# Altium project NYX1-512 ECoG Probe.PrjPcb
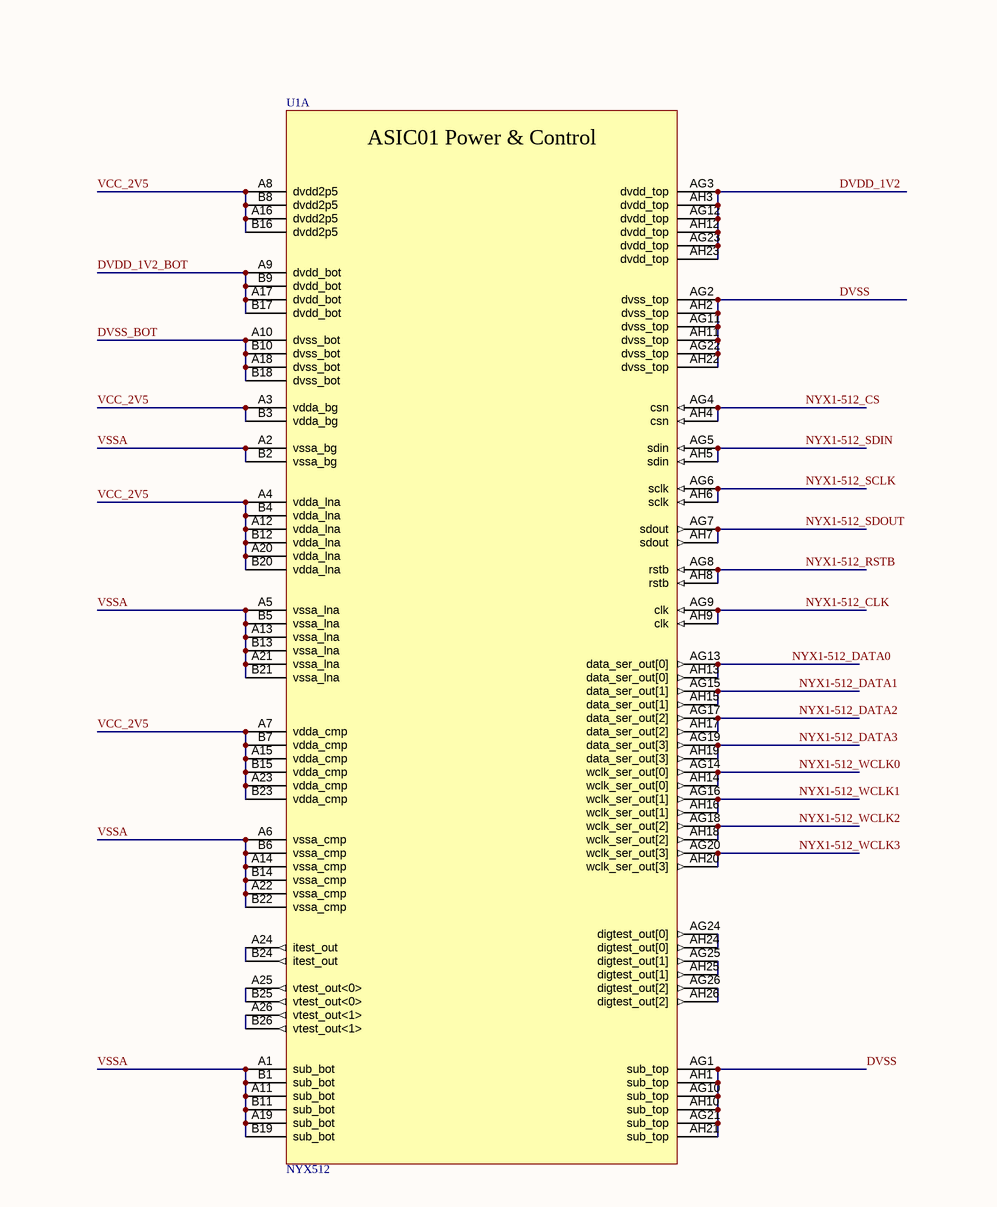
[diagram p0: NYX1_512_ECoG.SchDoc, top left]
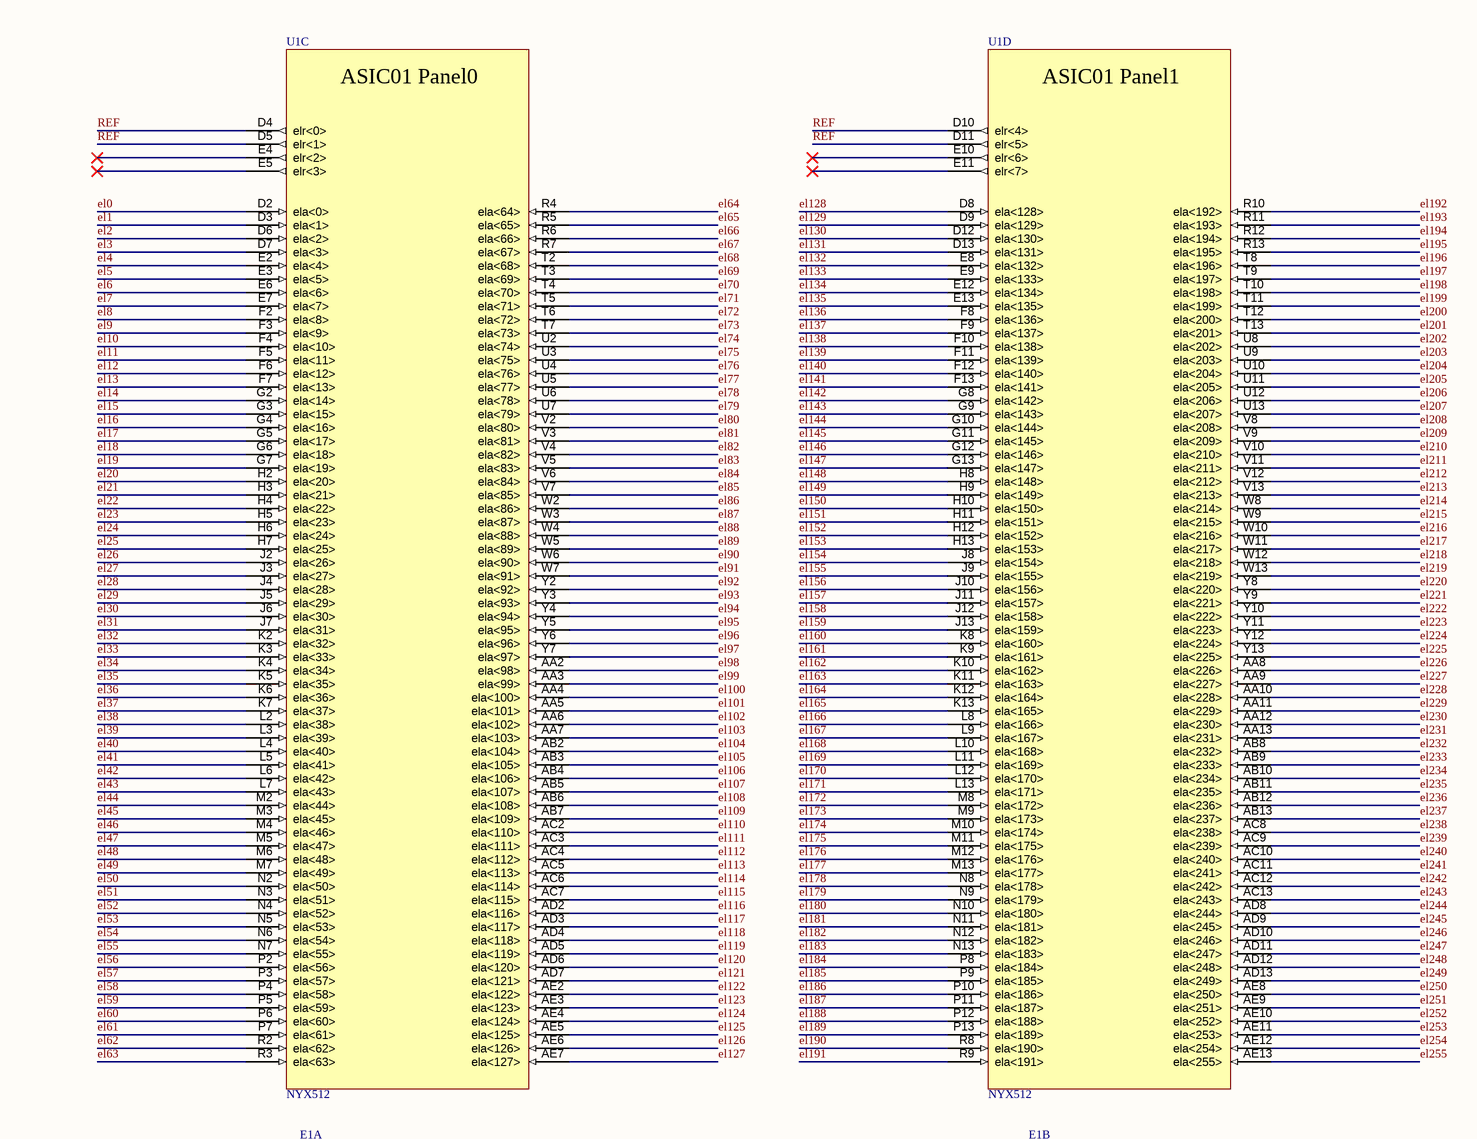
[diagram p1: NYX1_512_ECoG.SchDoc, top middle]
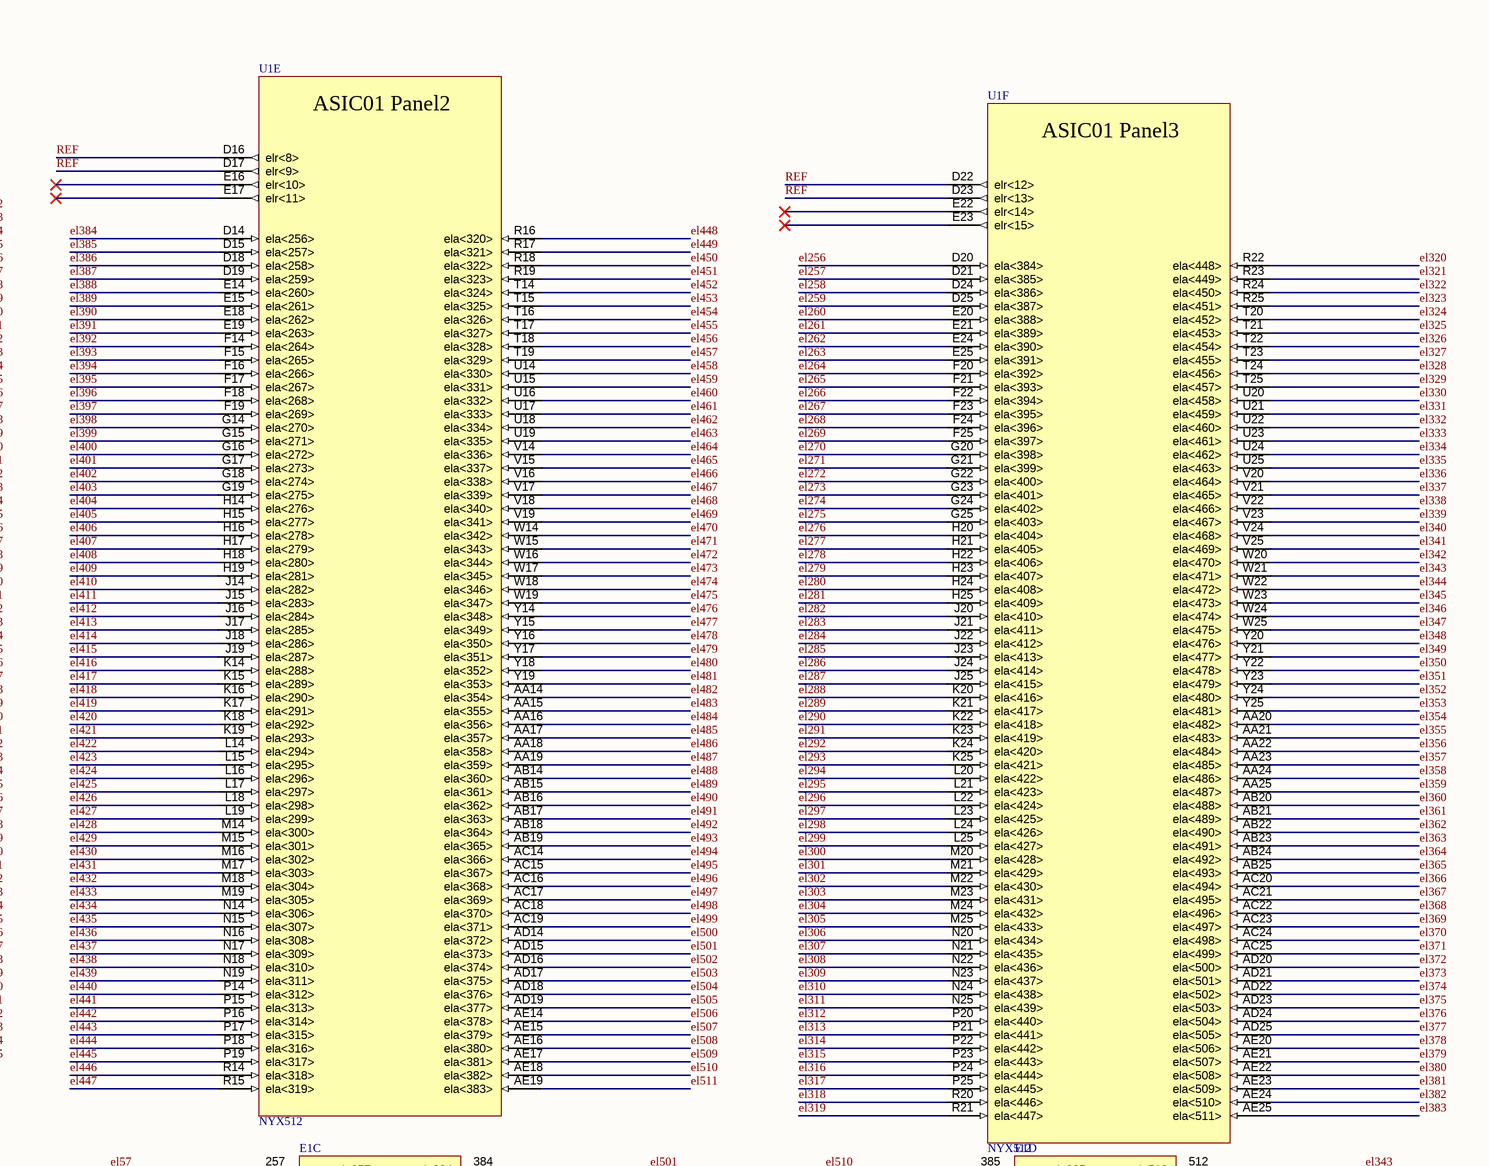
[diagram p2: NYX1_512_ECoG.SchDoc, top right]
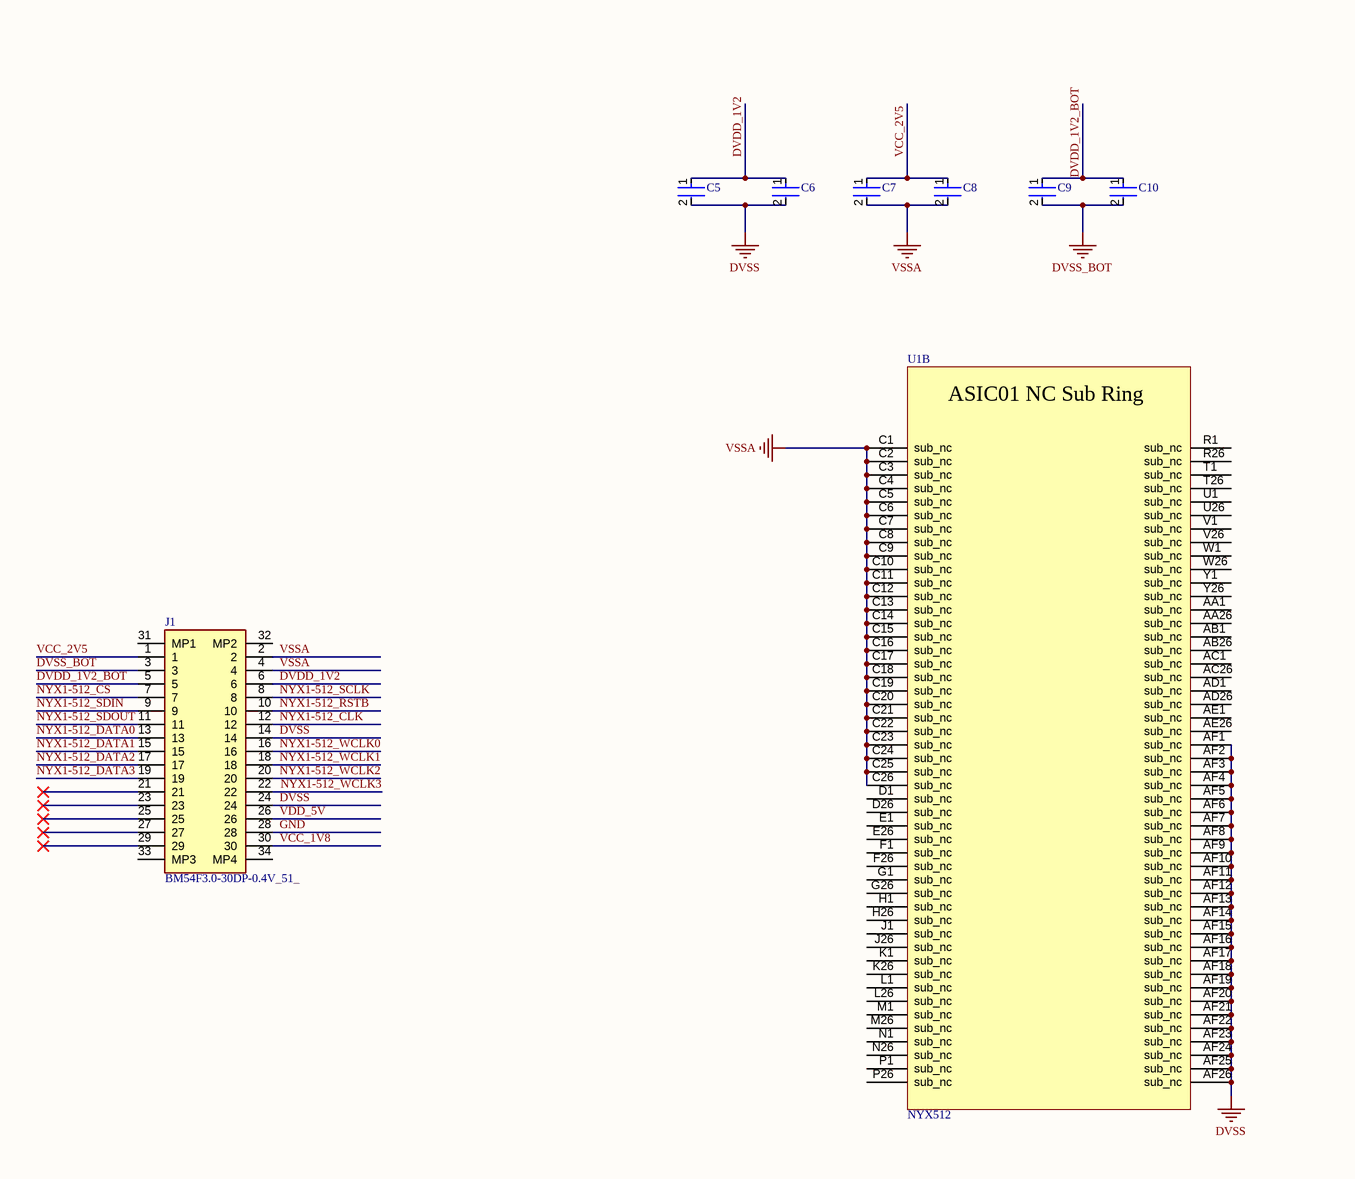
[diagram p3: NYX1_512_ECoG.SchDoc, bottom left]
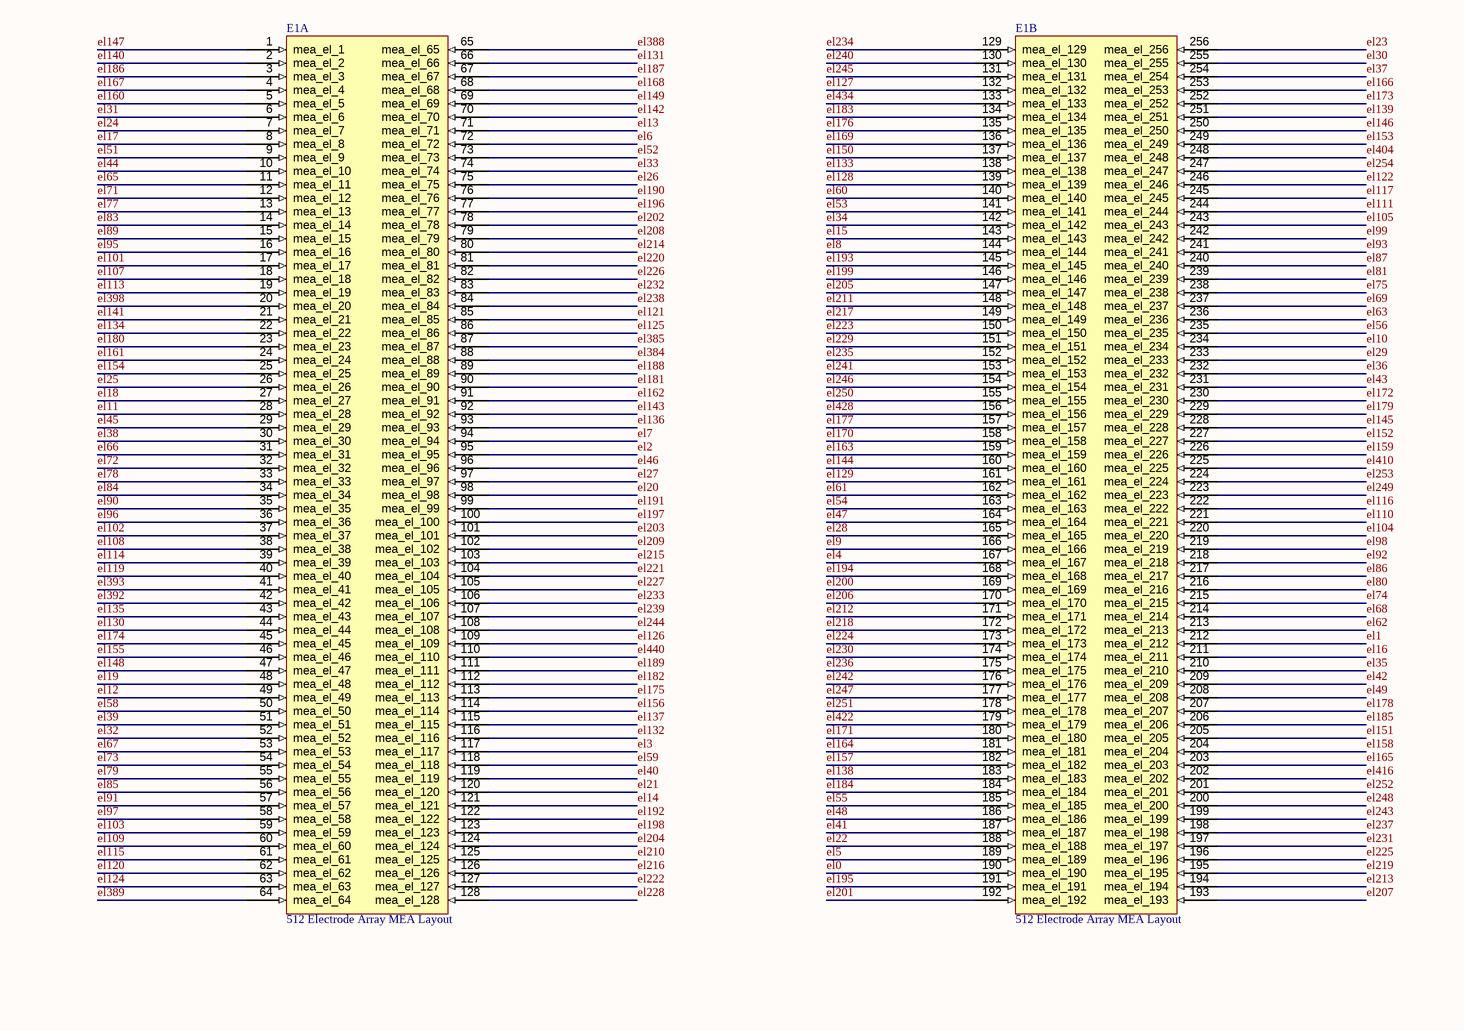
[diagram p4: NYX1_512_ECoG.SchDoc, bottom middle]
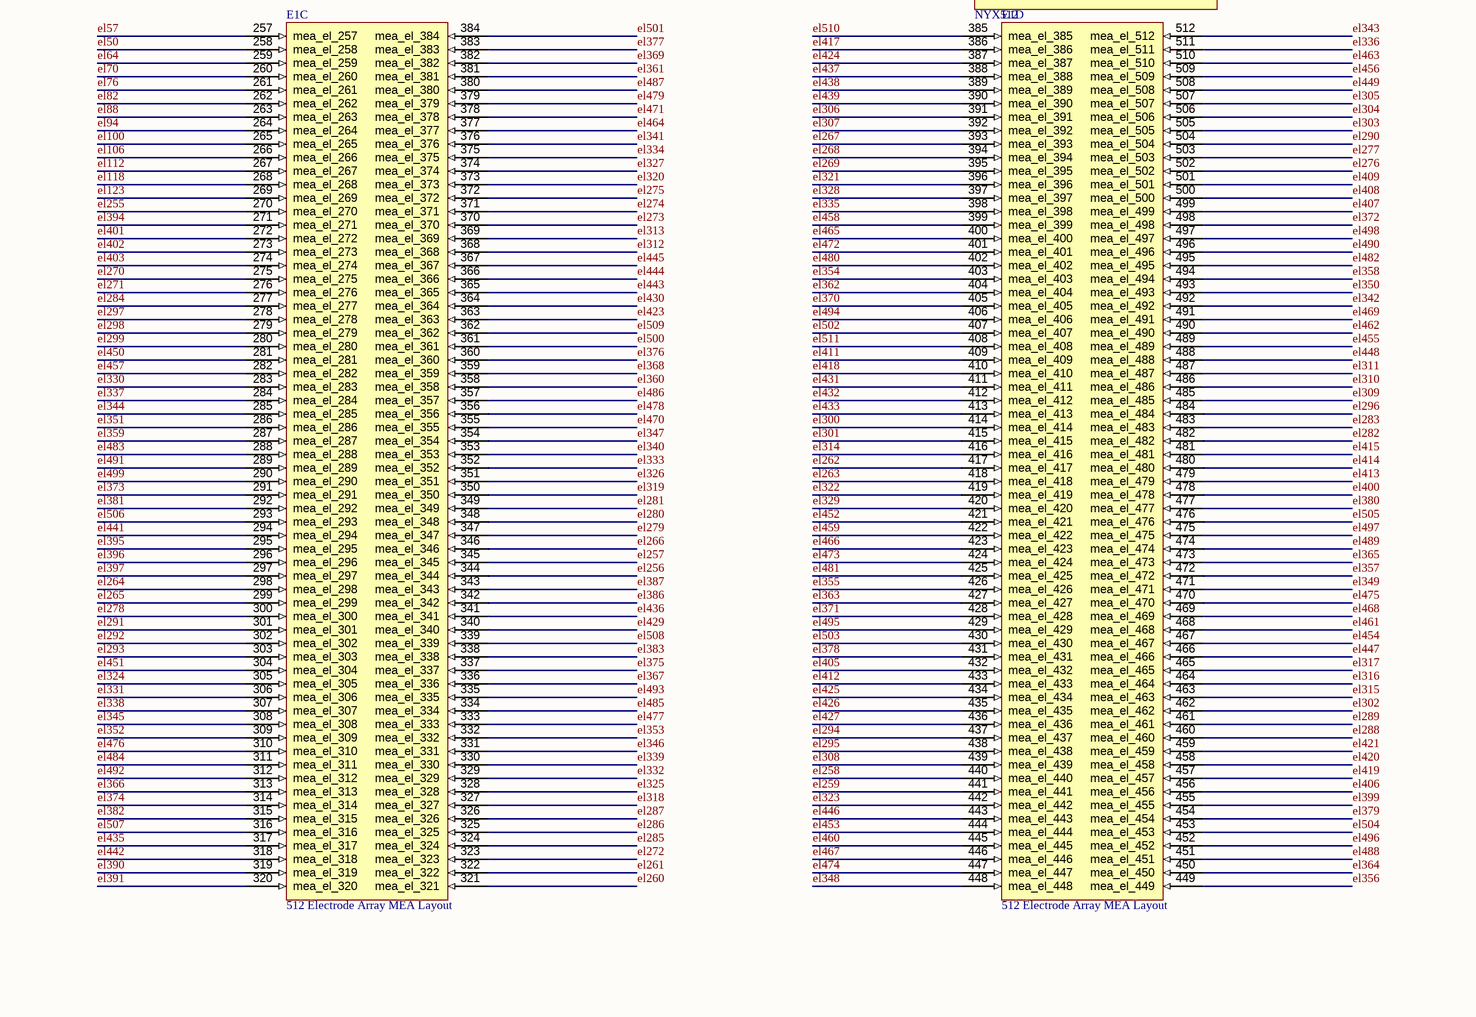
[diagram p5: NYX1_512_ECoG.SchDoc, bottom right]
Title: NYX1-512 ECoG Probe; Revision: A; Project: NYX1-512; Organization: Science Corporation; ENG_APP_DATE: 5/19/26; Engineer: Max Rothman; Address3: USA; Address2: Alameda CA 94501; Address1: 300 Wind River Way
1 sheet, 9 parts. Net scope: global (net labels, ports and power ports of the same name join across sheets).
Board file: NYX1_512_ECoG.PcbDoc

## Sheet NYX1_512_ECoG.SchDoc: NYX1-512 ECoG Probe
size 863 x 558 mm; SheetNumber: 2; SheetTotal: 2

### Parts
C5  GRT155R61E105KE01D  [FP-GRT155-0_05-MFG]  (value not drawn)
C6  CC0402KRX7R9BB104  [FP-CC0402-MFG]  (value not drawn)
C7  GRT155R61E105KE01D  [FP-GRT155-0_05-MFG]  (value not drawn)
C8  CC0402KRX7R9BB104  [FP-CC0402-MFG]  (value not drawn)
C9  GRT155R61E105KE01D  [FP-GRT155-0_05-MFG]  (value not drawn)
C10  CC0402KRX7R9BB104  [FP-CC0402-MFG]  (value not drawn)
E1  512 Electrode Array MEA Layout  [512 Electrode Array-Footprint-1]  (parts A,B,C,D of 4)
J1  BM54F3.0-30DP-0.4V_51_  [BM54F3030DP04V51]
U1  NYX512  [NYX512_footprint]  (parts A,B,C,D,E,F of 6)

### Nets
DVSS: C5.2 C6.2 J1.14 J1.24 U1.AF1(sub_nc) U1.AF2(sub_nc) U1.AF3(sub_nc) U1.AF4(sub_nc) U1.AF5(sub_nc) U1.AF6(sub_nc) U1.AF7(sub_nc) U1.AF8(sub_nc) U1.AF9(sub_nc) U1.AF10(sub_nc) U1.AF11(sub_nc) U1.AF12(sub_nc) U1.AF13(sub_nc) U1.AF14(sub_nc) U1.AF15(sub_nc) U1.AF16(sub_nc) U1.AF17(sub_nc) U1.AF18(sub_nc) U1.AF19(sub_nc) U1.AF20(sub_nc) U1.AF21(sub_nc) U1.AF22(sub_nc) U1.AF23(sub_nc) U1.AF24(sub_nc) U1.AF25(sub_nc) U1.AF26(sub_nc) U1.AG1(sub_top) U1.AG2(dvss_top) U1.AG10(sub_top) U1.AG11(dvss_top) U1.AG21(sub_top) U1.AG22(dvss_top) U1.AH1(sub_top) U1.AH2(dvss_top) U1.AH10(sub_top) U1.AH11(dvss_top) U1.AH21(sub_top) U1.AH22(dvss_top)
DVSS_BOT: C9.2 C10.2 J1.3 U1.A10(dvss_bot) U1.A18(dvss_bot) U1.B10(dvss_bot) U1.B18(dvss_bot)
VSSA: C7.2 C8.2 J1.2 J1.4 U1.A1(sub_bot) U1.A2(vssa_bg) U1.A5(vssa_lna) U1.A6(vssa_cmp) U1.A11(sub_bot) U1.A13(vssa_lna) U1.A14(vssa_cmp) U1.A19(sub_bot) U1.A21(vssa_lna) U1.A22(vssa_cmp) U1.B1(sub_bot) U1.B2(vssa_bg) U1.B5(vssa_lna) U1.B6(vssa_cmp) U1.B11(sub_bot) U1.B13(vssa_lna) U1.B14(vssa_cmp) U1.B19(sub_bot) U1.B21(vssa_lna) U1.B22(vssa_cmp) U1.C1(sub_nc) U1.C2(sub_nc) U1.C3(sub_nc) U1.C4(sub_nc) U1.C5(sub_nc) U1.C6(sub_nc) U1.C7(sub_nc) U1.C8(sub_nc) U1.C9(sub_nc) U1.C10(sub_nc) U1.C11(sub_nc) U1.C12(sub_nc) U1.C13(sub_nc) U1.C14(sub_nc) U1.C15(sub_nc) U1.C16(sub_nc) U1.C17(sub_nc) U1.C18(sub_nc) U1.C19(sub_nc) U1.C20(sub_nc) U1.C21(sub_nc) U1.C22(sub_nc) U1.C23(sub_nc) U1.C24(sub_nc) U1.C25(sub_nc) U1.C26(sub_nc)
DVDD_1V2: C5.1 C6.1 J1.6 U1.AG3(dvdd_top) U1.AG12(dvdd_top) U1.AG23(dvdd_top) U1.AH3(dvdd_top) U1.AH12(dvdd_top) U1.AH23(dvdd_top)
DVDD_1V2_BOT: C9.1 C10.1 J1.5 U1.A9(dvdd_bot) U1.A17(dvdd_bot) U1.B9(dvdd_bot) U1.B17(dvdd_bot)
el0: E1.190(mea_el_190) U1.D2(ela<0>)
el1: E1.212(mea_el_212) U1.D3(ela<1>)
el2: E1.95(mea_el_95) U1.D6(ela<2>)
el3: E1.117(mea_el_117) U1.D7(ela<3>)
el4: E1.167(mea_el_167) U1.E2(ela<4>)
el5: E1.189(mea_el_189) U1.E3(ela<5>)
el6: E1.72(mea_el_72) U1.E6(ela<6>)
el7: E1.94(mea_el_94) U1.E7(ela<7>)
el8: E1.144(mea_el_144) U1.F2(ela<8>)
el9: E1.166(mea_el_166) U1.F3(ela<9>)
el10: E1.234(mea_el_234) U1.F4(ela<10>)
el11: E1.28(mea_el_28) U1.F5(ela<11>)
el12: E1.49(mea_el_49) U1.F6(ela<12>)
el13: E1.71(mea_el_71) U1.F7(ela<13>)
el14: E1.121(mea_el_121) U1.G2(ela<14>)
el15: E1.143(mea_el_143) U1.G3(ela<15>)
el16: E1.211(mea_el_211) U1.G4(ela<16>)
el17: E1.8(mea_el_8) U1.G5(ela<17>)
el18: E1.27(mea_el_27) U1.G6(ela<18>)
el19: E1.48(mea_el_48) U1.G7(ela<19>)
el20: E1.98(mea_el_98) U1.H2(ela<20>)
el21: E1.120(mea_el_120) U1.H3(ela<21>)
el22: E1.188(mea_el_188) U1.H4(ela<22>)
el23: E1.256(mea_el_256) U1.H5(ela<23>)
el24: E1.7(mea_el_7) U1.H6(ela<24>)
el25: E1.26(mea_el_26) U1.H7(ela<25>)
el26: E1.75(mea_el_75) U1.J2(ela<26>)
el27: E1.97(mea_el_97) U1.J3(ela<27>)
el28: E1.165(mea_el_165) U1.J4(ela<28>)
el29: E1.233(mea_el_233) U1.J5(ela<29>)
el30: E1.255(mea_el_255) U1.J6(ela<30>)
el31: E1.6(mea_el_6) U1.J7(ela<31>)
el32: E1.52(mea_el_52) U1.K2(ela<32>)
el33: E1.74(mea_el_74) U1.K3(ela<33>)
el34: E1.142(mea_el_142) U1.K4(ela<34>)
el35: E1.210(mea_el_210) U1.K5(ela<35>)
el36: E1.232(mea_el_232) U1.K6(ela<36>)
el37: E1.254(mea_el_254) U1.K7(ela<37>)
el38: E1.30(mea_el_30) U1.L2(ela<38>)
el39: E1.51(mea_el_51) U1.L3(ela<39>)
el40: E1.119(mea_el_119) U1.L4(ela<40>)
el41: E1.187(mea_el_187) U1.L5(ela<41>)
el42: E1.209(mea_el_209) U1.L6(ela<42>)
el43: E1.231(mea_el_231) U1.L7(ela<43>)
el44: E1.10(mea_el_10) U1.M2(ela<44>)
el45: E1.29(mea_el_29) U1.M3(ela<45>)
el46: E1.96(mea_el_96) U1.M4(ela<46>)
el47: E1.164(mea_el_164) U1.M5(ela<47>)
el48: E1.186(mea_el_186) U1.M6(ela<48>)
el49: E1.208(mea_el_208) U1.M7(ela<49>)
el50: E1.258(mea_el_258) U1.N2(ela<50>)
el51: E1.9(mea_el_9) U1.N3(ela<51>)
el52: E1.73(mea_el_73) U1.N4(ela<52>)
el53: E1.141(mea_el_141) U1.N5(ela<53>)
el54: E1.163(mea_el_163) U1.N6(ela<54>)
el55: E1.185(mea_el_185) U1.N7(ela<55>)
el56: E1.235(mea_el_235) U1.P2(ela<56>)
el57: E1.257(mea_el_257) U1.P3(ela<57>)
el58: E1.50(mea_el_50) U1.P4(ela<58>)
el59: E1.118(mea_el_118) U1.P5(ela<59>)
el60: E1.140(mea_el_140) U1.P6(ela<60>)
el61: E1.162(mea_el_162) U1.P7(ela<61>)
el62: E1.213(mea_el_213) U1.R2(ela<62>)
el63: E1.236(mea_el_236) U1.R3(ela<63>)
el64: E1.259(mea_el_259) U1.R4(ela<64>)
el65: E1.11(mea_el_11) U1.R5(ela<65>)
el66: E1.31(mea_el_31) U1.R6(ela<66>)
el67: E1.53(mea_el_53) U1.R7(ela<67>)
el68: E1.214(mea_el_214) U1.T2(ela<68>)
el69: E1.237(mea_el_237) U1.T3(ela<69>)
el70: E1.260(mea_el_260) U1.T4(ela<70>)
el71: E1.12(mea_el_12) U1.T5(ela<71>)
el72: E1.32(mea_el_32) U1.T6(ela<72>)
el73: E1.54(mea_el_54) U1.T7(ela<73>)
el74: E1.215(mea_el_215) U1.U2(ela<74>)
el75: E1.238(mea_el_238) U1.U3(ela<75>)
el76: E1.261(mea_el_261) U1.U4(ela<76>)
el77: E1.13(mea_el_13) U1.U5(ela<77>)
el78: E1.33(mea_el_33) U1.U6(ela<78>)
el79: E1.55(mea_el_55) U1.U7(ela<79>)
el80: E1.216(mea_el_216) U1.V2(ela<80>)
el81: E1.239(mea_el_239) U1.V3(ela<81>)
el82: E1.262(mea_el_262) U1.V4(ela<82>)
el83: E1.14(mea_el_14) U1.V5(ela<83>)
el84: E1.34(mea_el_34) U1.V6(ela<84>)
el85: E1.56(mea_el_56) U1.V7(ela<85>)
el86: E1.217(mea_el_217) U1.W2(ela<86>)
el87: E1.240(mea_el_240) U1.W3(ela<87>)
el88: E1.263(mea_el_263) U1.W4(ela<88>)
el89: E1.15(mea_el_15) U1.W5(ela<89>)
el90: E1.35(mea_el_35) U1.W6(ela<90>)
el91: E1.57(mea_el_57) U1.W7(ela<91>)
el92: E1.218(mea_el_218) U1.Y2(ela<92>)
el93: E1.241(mea_el_241) U1.Y3(ela<93>)
el94: E1.264(mea_el_264) U1.Y4(ela<94>)
el95: E1.16(mea_el_16) U1.Y5(ela<95>)
el96: E1.36(mea_el_36) U1.Y6(ela<96>)
el97: E1.58(mea_el_58) U1.Y7(ela<97>)
el98: E1.219(mea_el_219) U1.AA2(ela<98>)
el99: E1.242(mea_el_242) U1.AA3(ela<99>)
el100: E1.265(mea_el_265) U1.AA4(ela<100>)
el101: E1.17(mea_el_17) U1.AA5(ela<101>)
el102: E1.37(mea_el_37) U1.AA6(ela<102>)
el103: E1.59(mea_el_59) U1.AA7(ela<103>)
el104: E1.220(mea_el_220) U1.AB2(ela<104>)
el105: E1.243(mea_el_243) U1.AB3(ela<105>)
el106: E1.266(mea_el_266) U1.AB4(ela<106>)
el107: E1.18(mea_el_18) U1.AB5(ela<107>)
el108: E1.38(mea_el_38) U1.AB6(ela<108>)
el109: E1.60(mea_el_60) U1.AB7(ela<109>)
el110: E1.221(mea_el_221) U1.AC2(ela<110>)
el111: E1.244(mea_el_244) U1.AC3(ela<111>)
el112: E1.267(mea_el_267) U1.AC4(ela<112>)
el113: E1.19(mea_el_19) U1.AC5(ela<113>)
el114: E1.39(mea_el_39) U1.AC6(ela<114>)
el115: E1.61(mea_el_61) U1.AC7(ela<115>)
el116: E1.222(mea_el_222) U1.AD2(ela<116>)
el117: E1.245(mea_el_245) U1.AD3(ela<117>)
el118: E1.268(mea_el_268) U1.AD4(ela<118>)
el119: E1.40(mea_el_40) U1.AD5(ela<119>)
el120: E1.62(mea_el_62) U1.AD6(ela<120>)
el121: E1.85(mea_el_85) U1.AD7(ela<121>)
el122: E1.246(mea_el_246) U1.AE2(ela<122>)
el123: E1.269(mea_el_269) U1.AE3(ela<123>)
el124: E1.63(mea_el_63) U1.AE4(ela<124>)
el125: E1.86(mea_el_86) U1.AE5(ela<125>)
el126: E1.109(mea_el_109) U1.AE6(ela<126>)
el127: E1.132(mea_el_132) U1.AE7(ela<127>)
el128: E1.139(mea_el_139) U1.D8(ela<128>)
el129: E1.161(mea_el_161) U1.D9(ela<129>)
el130: E1.44(mea_el_44) U1.D12(ela<130>)
el131: E1.66(mea_el_66) U1.D13(ela<131>)
el132: E1.116(mea_el_116) U1.E8(ela<132>)
el133: E1.138(mea_el_138) U1.E9(ela<133>)
el134: E1.22(mea_el_22) U1.E12(ela<134>)
el135: E1.43(mea_el_43) U1.E13(ela<135>)
el136: E1.93(mea_el_93) U1.F8(ela<136>)
el137: E1.115(mea_el_115) U1.F9(ela<137>)
el138: E1.183(mea_el_183) U1.F10(ela<138>)
el139: E1.251(mea_el_251) U1.F11(ela<139>)
el140: E1.2(mea_el_2) U1.F12(ela<140>)
el141: E1.21(mea_el_21) U1.F13(ela<141>)
el142: E1.70(mea_el_70) U1.G8(ela<142>)
el143: E1.92(mea_el_92) U1.G9(ela<143>)
el144: E1.160(mea_el_160) U1.G10(ela<144>)
el145: E1.228(mea_el_228) U1.G11(ela<145>)
el146: E1.250(mea_el_250) U1.G12(ela<146>)
el147: E1.1(mea_el_1) U1.G13(ela<147>)
el148: E1.47(mea_el_47) U1.H8(ela<148>)
el149: E1.69(mea_el_69) U1.H9(ela<149>)
el150: E1.137(mea_el_137) U1.H10(ela<150>)
el151: E1.205(mea_el_205) U1.H11(ela<151>)
el152: E1.227(mea_el_227) U1.H12(ela<152>)
el153: E1.249(mea_el_249) U1.H13(ela<153>)
el154: E1.25(mea_el_25) U1.J8(ela<154>)
el155: E1.46(mea_el_46) U1.J9(ela<155>)
el156: E1.114(mea_el_114) U1.J10(ela<156>)
el157: E1.182(mea_el_182) U1.J11(ela<157>)
el158: E1.204(mea_el_204) U1.J12(ela<158>)
el159: E1.226(mea_el_226) U1.J13(ela<159>)
el160: E1.5(mea_el_5) U1.K8(ela<160>)
el161: E1.24(mea_el_24) U1.K9(ela<161>)
el162: E1.91(mea_el_91) U1.K10(ela<162>)
el163: E1.159(mea_el_159) U1.K11(ela<163>)
el164: E1.181(mea_el_181) U1.K12(ela<164>)
el165: E1.203(mea_el_203) U1.K13(ela<165>)
el166: E1.253(mea_el_253) U1.L8(ela<166>)
el167: E1.4(mea_el_4) U1.L9(ela<167>)
el168: E1.68(mea_el_68) U1.L10(ela<168>)
el169: E1.136(mea_el_136) U1.L11(ela<169>)
el170: E1.158(mea_el_158) U1.L12(ela<170>)
el171: E1.180(mea_el_180) U1.L13(ela<171>)
el172: E1.230(mea_el_230) U1.M8(ela<172>)
el173: E1.252(mea_el_252) U1.M9(ela<173>)
el174: E1.45(mea_el_45) U1.M10(ela<174>)
el175: E1.113(mea_el_113) U1.M11(ela<175>)
el176: E1.135(mea_el_135) U1.M12(ela<176>)
el177: E1.157(mea_el_157) U1.M13(ela<177>)
el178: E1.207(mea_el_207) U1.N8(ela<178>)
el179: E1.229(mea_el_229) U1.N9(ela<179>)
el180: E1.23(mea_el_23) U1.N10(ela<180>)
el181: E1.90(mea_el_90) U1.N11(ela<181>)
el182: E1.112(mea_el_112) U1.N12(ela<182>)
el183: E1.134(mea_el_134) U1.N13(ela<183>)
el184: E1.184(mea_el_184) U1.P8(ela<184>)
el185: E1.206(mea_el_206) U1.P9(ela<185>)
el186: E1.3(mea_el_3) U1.P10(ela<186>)
el187: E1.67(mea_el_67) U1.P11(ela<187>)
el188: E1.89(mea_el_89) U1.P12(ela<188>)
el189: E1.111(mea_el_111) U1.P13(ela<189>)
el190: E1.76(mea_el_76) U1.R8(ela<190>)
el191: E1.99(mea_el_99) U1.R9(ela<191>)
el192: E1.122(mea_el_122) U1.R10(ela<192>)
el193: E1.145(mea_el_145) U1.R11(ela<193>)
el194: E1.168(mea_el_168) U1.R12(ela<194>)
el195: E1.191(mea_el_191) U1.R13(ela<195>)
el196: E1.77(mea_el_77) U1.T8(ela<196>)
el197: E1.100(mea_el_100) U1.T9(ela<197>)
el198: E1.123(mea_el_123) U1.T10(ela<198>)
el199: E1.146(mea_el_146) U1.T11(ela<199>)
el200: E1.169(mea_el_169) U1.T12(ela<200>)
el201: E1.192(mea_el_192) U1.T13(ela<201>)
el202: E1.78(mea_el_78) U1.U8(ela<202>)
el203: E1.101(mea_el_101) U1.U9(ela<203>)
el204: E1.124(mea_el_124) U1.U10(ela<204>)
el205: E1.147(mea_el_147) U1.U11(ela<205>)
el206: E1.170(mea_el_170) U1.U12(ela<206>)
el207: E1.193(mea_el_193) U1.U13(ela<207>)
el208: E1.79(mea_el_79) U1.V8(ela<208>)
el209: E1.102(mea_el_102) U1.V9(ela<209>)
el210: E1.125(mea_el_125) U1.V10(ela<210>)
el211: E1.148(mea_el_148) U1.V11(ela<211>)
el212: E1.171(mea_el_171) U1.V12(ela<212>)
el213: E1.194(mea_el_194) U1.V13(ela<213>)
el214: E1.80(mea_el_80) U1.W8(ela<214>)
el215: E1.103(mea_el_103) U1.W9(ela<215>)
el216: E1.126(mea_el_126) U1.W10(ela<216>)
el217: E1.149(mea_el_149) U1.W11(ela<217>)
el218: E1.172(mea_el_172) U1.W12(ela<218>)
el219: E1.195(mea_el_195) U1.W13(ela<219>)
el220: E1.81(mea_el_81) U1.Y8(ela<220>)
el221: E1.104(mea_el_104) U1.Y9(ela<221>)
el222: E1.127(mea_el_127) U1.Y10(ela<222>)
el223: E1.150(mea_el_150) U1.Y11(ela<223>)
el224: E1.173(mea_el_173) U1.Y12(ela<224>)
el225: E1.196(mea_el_196) U1.Y13(ela<225>)
el226: E1.82(mea_el_82) U1.AA8(ela<226>)
el227: E1.105(mea_el_105) U1.AA9(ela<227>)
el228: E1.128(mea_el_128) U1.AA10(ela<228>)
el229: E1.151(mea_el_151) U1.AA11(ela<229>)
el230: E1.174(mea_el_174) U1.AA12(ela<230>)
el231: E1.197(mea_el_197) U1.AA13(ela<231>)
el232: E1.83(mea_el_83) U1.AB8(ela<232>)
el233: E1.106(mea_el_106) U1.AB9(ela<233>)
el234: E1.129(mea_el_129) U1.AB10(ela<234>)
el235: E1.152(mea_el_152) U1.AB11(ela<235>)
el236: E1.175(mea_el_175) U1.AB12(ela<236>)
el237: E1.198(mea_el_198) U1.AB13(ela<237>)
el238: E1.84(mea_el_84) U1.AC8(ela<238>)
el239: E1.107(mea_el_107) U1.AC9(ela<239>)
el240: E1.130(mea_el_130) U1.AC10(ela<240>)
el241: E1.153(mea_el_153) U1.AC11(ela<241>)
el242: E1.176(mea_el_176) U1.AC12(ela<242>)
el243: E1.199(mea_el_199) U1.AC13(ela<243>)
el244: E1.108(mea_el_108) U1.AD8(ela<244>)
el245: E1.131(mea_el_131) U1.AD9(ela<245>)
el246: E1.154(mea_el_154) U1.AD10(ela<246>)
el247: E1.177(mea_el_177) U1.AD11(ela<247>)
el248: E1.200(mea_el_200) U1.AD12(ela<248>)
el249: E1.223(mea_el_223) U1.AD13(ela<249>)
el250: E1.155(mea_el_155) U1.AE8(ela<250>)
el251: E1.178(mea_el_178) U1.AE9(ela<251>)
el252: E1.201(mea_el_201) U1.AE10(ela<252>)
el253: E1.224(mea_el_224) U1.AE11(ela<253>)
el254: E1.247(mea_el_247) U1.AE12(ela<254>)
el255: E1.270(mea_el_270) U1.AE13(ela<255>)
el256: E1.344(mea_el_344) U1.D20(ela<384>)
el257: E1.345(mea_el_345) U1.D21(ela<385>)
el258: E1.440(mea_el_440) U1.D24(ela<386>)
el259: E1.441(mea_el_441) U1.D25(ela<387>)
el260: E1.321(mea_el_321) U1.E20(ela<388>)
el261: E1.322(mea_el_322) U1.E21(ela<389>)
el262: E1.417(mea_el_417) U1.E24(ela<390>)
el263: E1.418(mea_el_418) U1.E25(ela<391>)
el264: E1.298(mea_el_298) U1.F20(ela<392>)
el265: E1.299(mea_el_299) U1.F21(ela<393>)
el266: E1.346(mea_el_346) U1.F22(ela<394>)
el267: E1.393(mea_el_393) U1.F23(ela<395>)
el268: E1.394(mea_el_394) U1.F24(ela<396>)
el269: E1.395(mea_el_395) U1.F25(ela<397>)
el270: E1.275(mea_el_275) U1.G20(ela<398>)
el271: E1.276(mea_el_276) U1.G21(ela<399>)
el272: E1.323(mea_el_323) U1.G22(ela<400>)
el273: E1.370(mea_el_370) U1.G23(ela<401>)
el274: E1.371(mea_el_371) U1.G24(ela<402>)
el275: E1.372(mea_el_372) U1.G25(ela<403>)
el276: E1.502(mea_el_502) U1.H20(ela<404>)
el277: E1.503(mea_el_503) U1.H21(ela<405>)
el278: E1.300(mea_el_300) U1.H22(ela<406>)
el279: E1.347(mea_el_347) U1.H23(ela<407>)
el280: E1.348(mea_el_348) U1.H24(ela<408>)
el281: E1.349(mea_el_349) U1.H25(ela<409>)
el282: E1.482(mea_el_482) U1.J20(ela<410>)
el283: E1.483(mea_el_483) U1.J21(ela<411>)
el284: E1.277(mea_el_277) U1.J22(ela<412>)
el285: E1.324(mea_el_324) U1.J23(ela<413>)
el286: E1.325(mea_el_325) U1.J24(ela<414>)
el287: E1.326(mea_el_326) U1.J25(ela<415>)
el288: E1.460(mea_el_460) U1.K20(ela<416>)
el289: E1.461(mea_el_461) U1.K21(ela<417>)
el290: E1.504(mea_el_504) U1.K22(ela<418>)
el291: E1.301(mea_el_301) U1.K23(ela<419>)
el292: E1.302(mea_el_302) U1.K24(ela<420>)
el293: E1.303(mea_el_303) U1.K25(ela<421>)
el294: E1.437(mea_el_437) U1.L20(ela<422>)
el295: E1.438(mea_el_438) U1.L21(ela<423>)
el296: E1.484(mea_el_484) U1.L22(ela<424>)
el297: E1.278(mea_el_278) U1.L23(ela<425>)
el298: E1.279(mea_el_279) U1.L24(ela<426>)
el299: E1.280(mea_el_280) U1.L25(ela<427>)
el300: E1.414(mea_el_414) U1.M20(ela<428>)
el301: E1.415(mea_el_415) U1.M21(ela<429>)
el302: E1.462(mea_el_462) U1.M22(ela<430>)
el303: E1.505(mea_el_505) U1.M23(ela<431>)
el304: E1.506(mea_el_506) U1.M24(ela<432>)
el305: E1.507(mea_el_507) U1.M25(ela<433>)
el306: E1.391(mea_el_391) U1.N20(ela<434>)
el307: E1.392(mea_el_392) U1.N21(ela<435>)
el308: E1.439(mea_el_439) U1.N22(ela<436>)
el309: E1.485(mea_el_485) U1.N23(ela<437>)
el310: E1.486(mea_el_486) U1.N24(ela<438>)
el311: E1.487(mea_el_487) U1.N25(ela<439>)
el312: E1.368(mea_el_368) U1.P20(ela<440>)
el313: E1.369(mea_el_369) U1.P21(ela<441>)
el314: E1.416(mea_el_416) U1.P22(ela<442>)
el315: E1.463(mea_el_463) U1.P23(ela<443>)
el316: E1.464(mea_el_464) U1.P24(ela<444>)
el317: E1.465(mea_el_465) U1.P25(ela<445>)
el318: E1.327(mea_el_327) U1.R20(ela<446>)
el319: E1.350(mea_el_350) U1.R21(ela<447>)
el320: E1.373(mea_el_373) U1.R22(ela<448>)
el321: E1.396(mea_el_396) U1.R23(ela<449>)
el322: E1.419(mea_el_419) U1.R24(ela<450>)
el323: E1.442(mea_el_442) U1.R25(ela<451>)
el324: E1.305(mea_el_305) U1.T20(ela<452>)
el325: E1.328(mea_el_328) U1.T21(ela<453>)
el326: E1.351(mea_el_351) U1.T22(ela<454>)
el327: E1.374(mea_el_374) U1.T23(ela<455>)
el328: E1.397(mea_el_397) U1.T24(ela<456>)
el329: E1.420(mea_el_420) U1.T25(ela<457>)
el330: E1.283(mea_el_283) U1.U20(ela<458>)
el331: E1.306(mea_el_306) U1.U21(ela<459>)
el332: E1.329(mea_el_329) U1.U22(ela<460>)
el333: E1.352(mea_el_352) U1.U23(ela<461>)
el334: E1.375(mea_el_375) U1.U24(ela<462>)
el335: E1.398(mea_el_398) U1.U25(ela<463>)
el336: E1.511(mea_el_511) U1.V20(ela<464>)
el337: E1.284(mea_el_284) U1.V21(ela<465>)
el338: E1.307(mea_el_307) U1.V22(ela<466>)
el339: E1.330(mea_el_330) U1.V23(ela<467>)
el340: E1.353(mea_el_353) U1.V24(ela<468>)
el341: E1.376(mea_el_376) U1.V25(ela<469>)
el342: E1.492(mea_el_492) U1.W20(ela<470>)
el343: E1.512(mea_el_512) U1.W21(ela<471>)
el344: E1.285(mea_el_285) U1.W22(ela<472>)
el345: E1.308(mea_el_308) U1.W23(ela<473>)
el346: E1.331(mea_el_331) U1.W24(ela<474>)
el347: E1.354(mea_el_354) U1.W25(ela<475>)
el348: E1.448(mea_el_448) U1.Y20(ela<476>)
el349: E1.471(mea_el_471) U1.Y21(ela<477>)
el350: E1.493(mea_el_493) U1.Y22(ela<478>)
el351: E1.286(mea_el_286) U1.Y23(ela<479>)
el352: E1.309(mea_el_309) U1.Y24(ela<480>)
el353: E1.332(mea_el_332) U1.Y25(ela<481>)
el354: E1.403(mea_el_403) U1.AA20(ela<482>)
el355: E1.426(mea_el_426) U1.AA21(ela<483>)
el356: E1.449(mea_el_449) U1.AA22(ela<484>)
el357: E1.472(mea_el_472) U1.AA23(ela<485>)
el358: E1.494(mea_el_494) U1.AA24(ela<486>)
el359: E1.287(mea_el_287) U1.AA25(ela<487>)
el360: E1.358(mea_el_358) U1.AB20(ela<488>)
el361: E1.381(mea_el_381) U1.AB21(ela<489>)
el362: E1.404(mea_el_404) U1.AB22(ela<490>)
el363: E1.427(mea_el_427) U1.AB23(ela<491>)
el364: E1.450(mea_el_450) U1.AB24(ela<492>)
el365: E1.473(mea_el_473) U1.AB25(ela<493>)
el366: E1.313(mea_el_313) U1.AC20(ela<494>)
el367: E1.336(mea_el_336) U1.AC21(ela<495>)
el368: E1.359(mea_el_359) U1.AC22(ela<496>)
el369: E1.382(mea_el_382) U1.AC23(ela<497>)
el370: E1.405(mea_el_405) U1.AC24(ela<498>)
el371: E1.428(mea_el_428) U1.AC25(ela<499>)
el372: E1.498(mea_el_498) U1.AD20(ela<500>)
el373: E1.291(mea_el_291) U1.AD21(ela<501>)
el374: E1.314(mea_el_314) U1.AD22(ela<502>)
el375: E1.337(mea_el_337) U1.AD23(ela<503>)
el376: E1.360(mea_el_360) U1.AD24(ela<504>)
el377: E1.383(mea_el_383) U1.AD25(ela<505>)
el378: E1.431(mea_el_431) U1.AE20(ela<506>)
el379: E1.454(mea_el_454) U1.AE21(ela<507>)
el380: E1.477(mea_el_477) U1.AE22(ela<508>)
el381: E1.292(mea_el_292) U1.AE23(ela<509>)
el382: E1.315(mea_el_315) U1.AE24(ela<510>)
el383: E1.338(mea_el_338) U1.AE25(ela<511>)
el384: E1.88(mea_el_88) U1.D14(ela<256>)
el385: E1.87(mea_el_87) U1.D15(ela<257>)
el386: E1.342(mea_el_342) U1.D18(ela<258>)
el387: E1.343(mea_el_343) U1.D19(ela<259>)
el388: E1.65(mea_el_65) U1.E14(ela<260>)
el389: E1.64(mea_el_64) U1.E15(ela<261>)
el390: E1.319(mea_el_319) U1.E18(ela<262>)
el391: E1.320(mea_el_320) U1.E19(ela<263>)
el392: E1.42(mea_el_42) U1.F14(ela<264>)
el393: E1.41(mea_el_41) U1.F15(ela<265>)
el394: E1.271(mea_el_271) U1.F16(ela<266>)
el395: E1.295(mea_el_295) U1.F17(ela<267>)
el396: E1.296(mea_el_296) U1.F18(ela<268>)
el397: E1.297(mea_el_297) U1.F19(ela<269>)
el398: E1.20(mea_el_20) U1.G14(ela<270>)
el399: E1.455(mea_el_455) U1.G15(ela<271>)
el400: E1.478(mea_el_478) U1.G16(ela<272>)
el401: E1.272(mea_el_272) U1.G17(ela<273>)
el402: E1.273(mea_el_273) U1.G18(ela<274>)
el403: E1.274(mea_el_274) U1.G19(ela<275>)
el404: E1.248(mea_el_248) U1.H14(ela<276>)
el405: E1.432(mea_el_432) U1.H15(ela<277>)
el406: E1.456(mea_el_456) U1.H16(ela<278>)
el407: E1.499(mea_el_499) U1.H17(ela<279>)
el408: E1.500(mea_el_500) U1.H18(ela<280>)
el409: E1.501(mea_el_501) U1.H19(ela<281>)
el410: E1.225(mea_el_225) U1.J14(ela<282>)
el411: E1.409(mea_el_409) U1.J15(ela<283>)
el412: E1.433(mea_el_433) U1.J16(ela<284>)
el413: E1.479(mea_el_479) U1.J17(ela<285>)
el414: E1.480(mea_el_480) U1.J18(ela<286>)
el415: E1.481(mea_el_481) U1.J19(ela<287>)
el416: E1.202(mea_el_202) U1.K14(ela<288>)
el417: E1.386(mea_el_386) U1.K15(ela<289>)
el418: E1.410(mea_el_410) U1.K16(ela<290>)
el419: E1.457(mea_el_457) U1.K17(ela<291>)
el420: E1.458(mea_el_458) U1.K18(ela<292>)
el421: E1.459(mea_el_459) U1.K19(ela<293>)
el422: E1.179(mea_el_179) U1.L14(ela<294>)
el423: E1.363(mea_el_363) U1.L15(ela<295>)
el424: E1.387(mea_el_387) U1.L16(ela<296>)
el425: E1.434(mea_el_434) U1.L17(ela<297>)
el426: E1.435(mea_el_435) U1.L18(ela<298>)
el427: E1.436(mea_el_436) U1.L19(ela<299>)
el428: E1.156(mea_el_156) U1.M14(ela<300>)
el429: E1.340(mea_el_340) U1.M15(ela<301>)
el430: E1.364(mea_el_364) U1.M16(ela<302>)
el431: E1.411(mea_el_411) U1.M17(ela<303>)
el432: E1.412(mea_el_412) U1.M18(ela<304>)
el433: E1.413(mea_el_413) U1.M19(ela<305>)
el434: E1.133(mea_el_133) U1.N14(ela<306>)
el435: E1.317(mea_el_317) U1.N15(ela<307>)
el436: E1.341(mea_el_341) U1.N16(ela<308>)
el437: E1.388(mea_el_388) U1.N17(ela<309>)
el438: E1.389(mea_el_389) U1.N18(ela<310>)
el439: E1.390(mea_el_390) U1.N19(ela<311>)
el440: E1.110(mea_el_110) U1.P14(ela<312>)
el441: E1.294(mea_el_294) U1.P15(ela<313>)
el442: E1.318(mea_el_318) U1.P16(ela<314>)
el443: E1.365(mea_el_365) U1.P17(ela<315>)
el444: E1.366(mea_el_366) U1.P18(ela<316>)
el445: E1.367(mea_el_367) U1.P19(ela<317>)
el446: E1.443(mea_el_443) U1.R14(ela<318>)
el447: E1.466(mea_el_466) U1.R15(ela<319>)
el448: E1.488(mea_el_488) U1.R16(ela<320>)
el449: E1.508(mea_el_508) U1.R17(ela<321>)
el450: E1.281(mea_el_281) U1.R18(ela<322>)
el451: E1.304(mea_el_304) U1.R19(ela<323>)
el452: E1.421(mea_el_421) U1.T14(ela<324>)
el453: E1.444(mea_el_444) U1.T15(ela<325>)
el454: E1.467(mea_el_467) U1.T16(ela<326>)
el455: E1.489(mea_el_489) U1.T17(ela<327>)
el456: E1.509(mea_el_509) U1.T18(ela<328>)
el457: E1.282(mea_el_282) U1.T19(ela<329>)
el458: E1.399(mea_el_399) U1.U14(ela<330>)
el459: E1.422(mea_el_422) U1.U15(ela<331>)
el460: E1.445(mea_el_445) U1.U16(ela<332>)
el461: E1.468(mea_el_468) U1.U17(ela<333>)
el462: E1.490(mea_el_490) U1.U18(ela<334>)
el463: E1.510(mea_el_510) U1.U19(ela<335>)
el464: E1.377(mea_el_377) U1.V14(ela<336>)
el465: E1.400(mea_el_400) U1.V15(ela<337>)
el466: E1.423(mea_el_423) U1.V16(ela<338>)
el467: E1.446(mea_el_446) U1.V17(ela<339>)
el468: E1.469(mea_el_469) U1.V18(ela<340>)
el469: E1.491(mea_el_491) U1.V19(ela<341>)
el470: E1.355(mea_el_355) U1.W14(ela<342>)
el471: E1.378(mea_el_378) U1.W15(ela<343>)
el472: E1.401(mea_el_401) U1.W16(ela<344>)
el473: E1.424(mea_el_424) U1.W17(ela<345>)
el474: E1.447(mea_el_447) U1.W18(ela<346>)
el475: E1.470(mea_el_470) U1.W19(ela<347>)
el476: E1.310(mea_el_310) U1.Y14(ela<348>)
el477: E1.333(mea_el_333) U1.Y15(ela<349>)
el478: E1.356(mea_el_356) U1.Y16(ela<350>)
el479: E1.379(mea_el_379) U1.Y17(ela<351>)
el480: E1.402(mea_el_402) U1.Y18(ela<352>)
el481: E1.425(mea_el_425) U1.Y19(ela<353>)
el482: E1.495(mea_el_495) U1.AA14(ela<354>)
el483: E1.288(mea_el_288) U1.AA15(ela<355>)
el484: E1.311(mea_el_311) U1.AA16(ela<356>)
el485: E1.334(mea_el_334) U1.AA17(ela<357>)
el486: E1.357(mea_el_357) U1.AA18(ela<358>)
el487: E1.380(mea_el_380) U1.AA19(ela<359>)
el488: E1.451(mea_el_451) U1.AB14(ela<360>)
el489: E1.474(mea_el_474) U1.AB15(ela<361>)
el490: E1.496(mea_el_496) U1.AB16(ela<362>)
el491: E1.289(mea_el_289) U1.AB17(ela<363>)
el492: E1.312(mea_el_312) U1.AB18(ela<364>)
el493: E1.335(mea_el_335) U1.AB19(ela<365>)
el494: E1.406(mea_el_406) U1.AC14(ela<366>)
el495: E1.429(mea_el_429) U1.AC15(ela<367>)
el496: E1.452(mea_el_452) U1.AC16(ela<368>)
el497: E1.475(mea_el_475) U1.AC17(ela<369>)
el498: E1.497(mea_el_497) U1.AC18(ela<370>)
el499: E1.290(mea_el_290) U1.AC19(ela<371>)
el500: E1.361(mea_el_361) U1.AD14(ela<372>)
el501: E1.384(mea_el_384) U1.AD15(ela<373>)
el502: E1.407(mea_el_407) U1.AD16(ela<374>)
el503: E1.430(mea_el_430) U1.AD17(ela<375>)
el504: E1.453(mea_el_453) U1.AD18(ela<376>)
el505: E1.476(mea_el_476) U1.AD19(ela<377>)
el506: E1.293(mea_el_293) U1.AE14(ela<378>)
el507: E1.316(mea_el_316) U1.AE15(ela<379>)
el508: E1.339(mea_el_339) U1.AE16(ela<380>)
el509: E1.362(mea_el_362) U1.AE17(ela<381>)
el510: E1.385(mea_el_385) U1.AE18(ela<382>)
el511: E1.408(mea_el_408) U1.AE19(ela<383>)
GND: J1.28
NYX1-512_CLK: J1.12 U1.AG9(clk) U1.AH9(clk)
NYX1-512_CS: J1.7 U1.AG4(csn) U1.AH4(csn)
NYX1-512_DATA0: J1.13 U1.AG13(data_ser_out[0]) U1.AH13(data_ser_out[0])
NYX1-512_DATA1: J1.15 U1.AG15(data_ser_out[1]) U1.AH15(data_ser_out[1])
NYX1-512_DATA2: J1.17 U1.AG17(data_ser_out[2]) U1.AH17(data_ser_out[2])
NYX1-512_DATA3: J1.19 U1.AG19(data_ser_out[3]) U1.AH19(data_ser_out[3])
NYX1-512_RSTB: J1.10 U1.AG8(rstb) U1.AH8(rstb)
NYX1-512_SCLK: J1.8 U1.AG6(sclk) U1.AH6(sclk)
NYX1-512_SDIN: J1.9 U1.AG5(sdin) U1.AH5(sdin)
NYX1-512_SDOUT: J1.11 U1.AG7(sdout) U1.AH7(sdout)
NYX1-512_WCLK0: J1.16 U1.AG14(wclk_ser_out[0]) U1.AH14(wclk_ser_out[0])
NYX1-512_WCLK1: J1.18 U1.AG16(wclk_ser_out[1]) U1.AH16(wclk_ser_out[1])
NYX1-512_WCLK2: J1.20 U1.AG18(wclk_ser_out[2]) U1.AH18(wclk_ser_out[2])
NYX1-512_WCLK3: J1.22 U1.AG20(wclk_ser_out[3]) U1.AH20(wclk_ser_out[3])
REF: U1.D4(elr<0>) U1.D5(elr<1>) U1.D10(elr<4>) U1.D11(elr<5>) U1.D16(elr<8>) U1.D17(elr<9>) U1.D22(elr<12>) U1.D23(elr<13>)
VCC_1V8: J1.30
VCC_2V5: C7.1 C8.1 J1.1 U1.A3(vdda_bg) U1.A4(vdda_lna) U1.A7(vdda_cmp) U1.A8(dvdd2p5) U1.A12(vdda_lna) U1.A15(vdda_cmp) U1.A16(dvdd2p5) U1.A20(vdda_lna) U1.A23(vdda_cmp) U1.B3(vdda_bg) U1.B4(vdda_lna) U1.B7(vdda_cmp) U1.B8(dvdd2p5) U1.B12(vdda_lna) U1.B15(vdda_cmp) U1.B16(dvdd2p5) U1.B20(vdda_lna) U1.B23(vdda_cmp)
VDD_5V: J1.26
NetU1_A24: U1.A24(itest_out) U1.B24(itest_out)
NetU1_A25: U1.A25(vtest_out<0>) U1.B25(vtest_out<0>)
NetU1_A26: U1.A26(vtest_out<1>) U1.B26(vtest_out<1>)
NetU1_AG24: U1.AG24(digtest_out[0]) U1.AH24(digtest_out[0])
NetU1_AG25: U1.AG25(digtest_out[1]) U1.AH25(digtest_out[1])
NetU1_AG26: U1.AG26(digtest_out[2]) U1.AH26(digtest_out[2])

Not connected (* = marked no-connect by the designer): J1 21* 23* 25* 27* 29* 31(MP1) 32(MP2) 33(MP3) 34(MP4); U1 AA1(sub_nc) AA26(sub_nc) AB1(sub_nc) AB26(sub_nc) AC1(sub_nc) AC26(sub_nc) AD1(sub_nc) AD26(sub_nc) AE1(sub_nc) AE26(sub_nc) D1(sub_nc) D26(sub_nc) E1(sub_nc) E4(elr<2>)* E5(elr<3>)* E10(elr<6>)* E11(elr<7>)* E16(elr<10>)* E17(elr<11>)* E22(elr<14>)* E23(elr<15>)* E26(sub_nc) F1(sub_nc) F26(sub_nc) G1(sub_nc) G26(sub_nc) H1(sub_nc) H26(sub_nc) J1(sub_nc) J26(sub_nc) K1(sub_nc) K26(sub_nc) L1(sub_nc) L26(sub_nc) M1(sub_nc) M26(sub_nc) N1(sub_nc) N26(sub_nc) P1(sub_nc) P26(sub_nc) R1(sub_nc) R26(sub_nc) T1(sub_nc) T26(sub_nc) U1(sub_nc) U26(sub_nc) V1(sub_nc) V26(sub_nc) W1(sub_nc) W26(sub_nc) Y1(sub_nc) Y26(sub_nc)

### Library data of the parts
C5 C7 C9 = CMP-06035-018811-1: Multi-Layer Ceramic Capacitor 1uF 25V X5R ±10% 0402 Paper T/R
C6 C8 C10 = CMP-03422-001010-1: CAP CER 0.1UF 50V X7R 0402; Manufacturer: YAGEO; Capacitance: 100 nF; Temperature Coefficient: 30ppm/°C; Material: Ceramic; Value: 100 nF; Automotive Grade: NA; Tolerance: 0.1
E1 = CMP-00022-1: 20x20 um electrodes, 150 um pitch
J1 = CMP-290-000006-2: Board to Board & Mezzanine Connectors Plug; Manufacturer_Name: Hirose; Manufacturer_Part_Number: BM54F3.0-30DP-0.4V(51)
U1 = CMP-031-00061-2: ASIC01 512 electrode neural recording IC; MPN: ASIC01(SCIENCE); ENG: Marat Rostov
